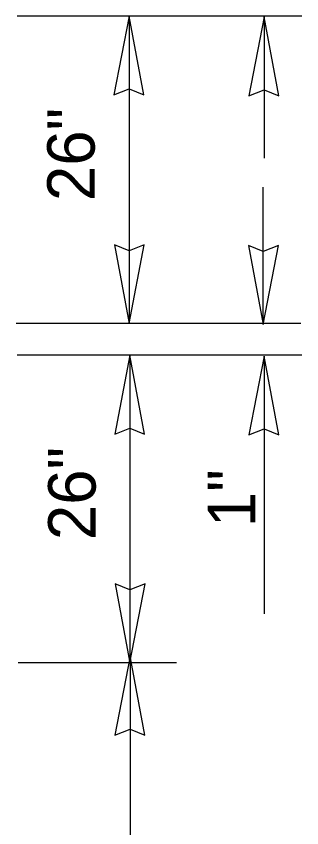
# Model space of a CAD drawing. Extents: x 52649 to 53276, y 9410 to 9783.
# Drawn here: x 52887.78 to 52903.56, y 9671.64 to 9716.48 of the extents above; entities that cross this region are included whole.
import ezdxf

# ---------------------------------------------------------------- set-up
doc = ezdxf.new("R2010")
doc.units = 0
doc.layers.add('DimLines_dp', color=7, linetype='Continuous')

msp = doc.modelspace()

# ---------------------------------------------------------------- linework, layer by layer
at = {"layer": 'DimLines_dp'}
for p, q in [((52903.56, 9716.477), (52887.832, 9716.477)), ((52894.014, 9716.477), (52893.174, 9712.127)), ((52894.014, 9716.477), (52893.174, 9712.127)), ((52894.014, 9716.477), (52894.014, 9699.493)), ((52894.824, 9712.127), (52894.014, 9716.477)), ((52894.824, 9712.127), (52894.014, 9716.477)), ((52901.482, 9716.437), (52900.642, 9712.087)), ((52901.482, 9716.437), (52901.482, 9708.64)), ((52902.292, 9712.087), (52901.482, 9716.437)), ((52893.174, 9712.127), (52894.014, 9712.457)), ((52893.174, 9712.127), (52894.014, 9712.457)), ((52894.014, 9712.457), (52894.824, 9712.127)), ((52894.014, 9712.457), (52894.824, 9712.127)), ((52900.642, 9712.087), (52901.482, 9712.417)), ((52901.482, 9712.417), (52902.292, 9712.087)), ((52901.429, 9699.453), (52901.429, 9707.035)), ((52894.014, 9703.513), (52893.204, 9703.843)), ((52893.204, 9703.843), (52894.014, 9699.493)), ((52894.014, 9703.513), (52893.204, 9703.843)), ((52893.204, 9703.843), (52894.014, 9699.493)), ((52894.014, 9699.493), (52894.854, 9703.843)), ((52894.854, 9703.843), (52894.014, 9703.513)), ((52894.014, 9699.493), (52894.854, 9703.843)), ((52894.854, 9703.843), (52894.014, 9703.513)), ((52901.429, 9703.473), (52900.619, 9703.803)), ((52900.619, 9703.803), (52901.429, 9699.453)), ((52901.429, 9699.453), (52902.269, 9703.803)), ((52902.269, 9703.803), (52901.429, 9703.473)), ((52903.507, 9699.493), (52887.779, 9699.493)), ((52903.56, 9697.743), (52887.832, 9697.743)), ((52894.066, 9697.743), (52893.226, 9693.393)), ((52894.066, 9697.743), (52894.066, 9680.759)), ((52894.876, 9693.393), (52894.066, 9697.743)), ((52901.482, 9697.703), (52900.642, 9693.353)), ((52901.482, 9697.703), (52901.482, 9683.463)), ((52902.292, 9693.353), (52901.482, 9697.703)), ((52893.226, 9693.393), (52894.066, 9693.723)), ((52894.066, 9693.723), (52894.876, 9693.393)), ((52900.642, 9693.353), (52901.482, 9693.683)), ((52901.482, 9693.683), (52902.292, 9693.353)), ((52894.066, 9684.779), (52893.256, 9685.109)), ((52893.256, 9685.109), (52894.066, 9680.759)), ((52894.066, 9684.779), (52893.256, 9685.109)), ((52893.256, 9685.109), (52894.066, 9680.759)), ((52894.066, 9680.759), (52894.906, 9685.109)), ((52894.906, 9685.109), (52894.066, 9684.779)), ((52894.066, 9680.759), (52894.906, 9685.109)), ((52894.906, 9685.109), (52894.066, 9684.779)), ((52894.069, 9681.11), (52893.229, 9676.76)), ((52894.069, 9681.11), (52894.069, 9631.097)), ((52894.879, 9676.76), (52894.069, 9681.11)), ((52896.64, 9680.759), (52887.884, 9680.759)), ((52893.229, 9676.76), (52894.069, 9677.09)), ((52894.069, 9677.09), (52894.879, 9676.76))]:
    msp.add_line(p, q, dxfattribs=at)

# ---------------------------------------------------------------- texts
for s, p in [('26"', (52892.116, 9706.266)), ('26"', (52892.168, 9687.532)), ('1"', (52900.993, 9688.247))]:
    msp.add_text(s, height=2.625, rotation=90, dxfattribs=at).set_placement(p)

doc.saveas('drawing.dxf')
